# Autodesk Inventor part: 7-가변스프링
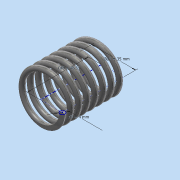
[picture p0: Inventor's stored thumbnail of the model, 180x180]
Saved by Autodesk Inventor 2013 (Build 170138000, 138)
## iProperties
Created: 2015-01
Part Number: 7-가변스프링
Material: 강철, 탄소
Document SubType Name: Modeling
Designer: WINDOWS7
Density: 7.87 g/cm^3
Mass: 80.1205 g
Surface Area: 103.229 cm^2
Volume: 10.1805 cm^3
Author: WINDOWS7
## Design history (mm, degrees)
sketch "스케치1"
  geometry: L1 (0, 0)-(17.5, 0); L2 (17.5, 0)-(17.5, 48.5); L3 (17.5, 48.5)-(0, 48.5); L4 (0, 48.5)-(0, 0); C1 r 2 at (17.5, 0)
  constraints: 8 end point, 2 parallel, 1 centre point, 1 coincident, 1 horizontal, 1 perpendicular
  dimensions: "d0" = 48.5 distance of L3.end L1.start (derived); "d1" = 35 diameter of L2 L4; "d2" = 4 diameter of C1
feature "코일1" pitch "d3" = 10; turns "d5" = 7.5; dims "d4" = 48.5 (= d0), "d6" = 0, angle "d7" = 90 deg, angle "d8" = 90 deg, "d9" = 0, "d10" = 0
node "작업 평면1"
sketch "스케치2"
  geometry: L1 (-19.5, 0)-(-15.5, 0) reference; 1 further point
  constraints: 1 horizontal alignment
extrude "돌출1" cut sketch "스케치2" distance "d12" = 10; taper "d13" = 0 deg
node "작업 평면2"
sketch "스케치3"
  geometry: L1 (15.5, 0)-(19.5, 0) reference; 1 further point
  constraints: 1 horizontal alignment
extrude "돌출2" cut sketch "스케치3" distance "d15" = 10; taper "d16" = 0 deg
node "솔리드1"
node "절단 모서리 투영1"
node "절단 모서리 투영2"
other parameters: "d11" = 0, "d14" = 48.5 (= d0)
